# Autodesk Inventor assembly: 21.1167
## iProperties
Created: 2007-03
Part Number: 21.1167
Document SubType Name: Assembly
Designer: Andy Moles
Description: ROD CAM ADAPTOR
Vendor: S
Translation Standard: STEP AP214IS
File Name: 1000-U49_ASM
Preprocessor: PRO/ENGINEER BY PARAMETRIC TECHNOLOGY CORPORATION, 2005310
Postprocessor: Build: 344b, Release: 11 SP2 - Date: Fri 08/18/2006
Sent Units: MILLIMETERS
Uncertainty: 0.004211719462213
Author: Andy Moles
